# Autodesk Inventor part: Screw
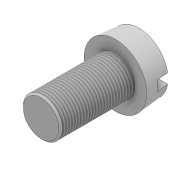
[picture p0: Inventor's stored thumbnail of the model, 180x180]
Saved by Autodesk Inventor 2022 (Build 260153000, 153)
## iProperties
Created: 2016-05
Part Number: Screw
Material: Generic
Document SubType Name: Modeling
Designer: CADCIM
Density: 1 g/cm^3
Appearance: Default
Author: CADCIM
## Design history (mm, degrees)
sketch "Sketch1"
  geometry: C1 r 16 at (0, 0); 1 further point
  constraints: 1 centre point, 1 coincident
  dimensions: "d0" = 32 diameter of C1
extrude "Extrusion1" new body sketch "Sketch1" distance "d1" = 12; taper "d2" = -5 deg
sketch "Sketch2"
  geometry: C1 r 10 at (0, 0); 1 further point
  constraints: 1 centre point, 1 coincident
  dimensions: "d4" = 20 diameter of C1
extrude "Extrusion2" join sketch "Sketch2" distance "d5" = 38; taper "d6" = 0 deg
workplane "Work Plane1"
thread "Thread1" dims "d10" = 10, "d11" = 0
chamfer "Chamfer1" distance "d12" = 0.9; stored, may be unused: second distance "d13" = 2, angle "d14" = 45 deg
sketch "Sketch4"
  geometry: L1 (-19.014, -2.5)-(20.179, -2.5); L2 (20.179, -2.5)-(20.179, 2.5); L3 (20.179, 2.5)-(-19.014, 2.5); L4 (-19.014, 2.5)-(-19.014, -2.5); L5 (0, 0)-(-19.039, 0)
  constraints: 10 end point, 2 horizontal, 2 parallel, 1 perpendicular, 1 other
  dimensions: "d15" = 5 distance of L3.end L1.start
extrude "Extrusion4" cut sketch "Sketch4" distance "d16" = 6; taper "d17" = 0 deg
body "Solid1"
